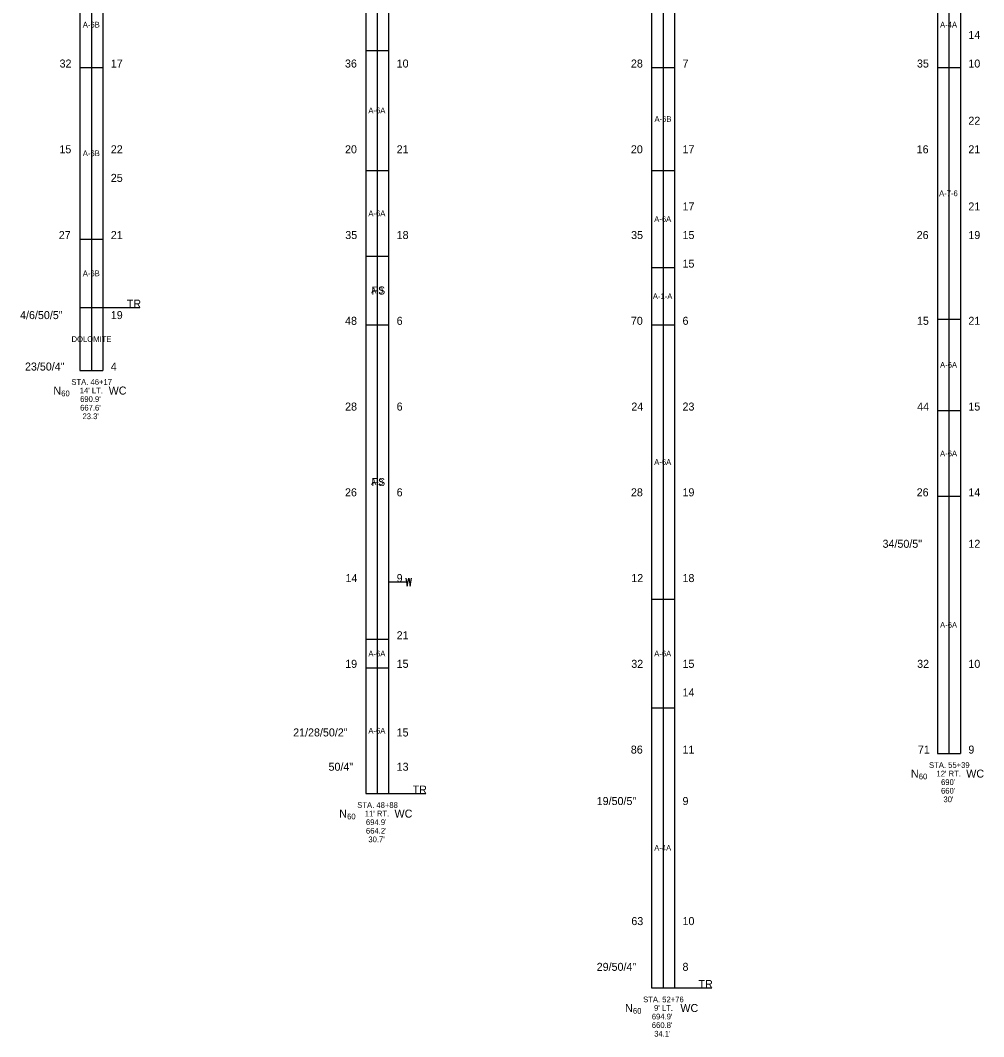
# Model space of a CAD drawing. Extents: x -1.2 to 16, y -0.9 to 35.
# Drawn here: x -1.24 to 15.61, y -0.85 to 16.93 of the extents above; entities that cross this region are included whole.
import ezdxf

# ---------------------------------------------------------------- set-up
doc = ezdxf.new("R2010")
doc.units = 0
for name, color, linetype in [('GT_Project_Cells', 7, 'Continuous'), ('GT_Project_Soil_Boring', 7, 'Continuous'), ('GT_Project_Soil_Layers', 7, 'Continuous'), ('GT_Project_Text', 7, 'Continuous'), ('SC_Scratch1', 7, 'Continuous'), ('SC_Scratch2', 7, 'Continuous')]:
    doc.layers.add(name, color=color, linetype=linetype)

msp = doc.modelspace()

# ---------------------------------------------------------------- linework, layer by layer
at = {"layer": 'GT_Project_Cells'}
msp.add_line((5.5, 7.1), (5.2, 7.1), dxfattribs=at)
msp.add_lwpolyline([(5.503, 7.171), (5.524, 7.031), (5.551, 7.171), (5.579, 7.031), (5.601, 7.171)], dxfattribs=at)
at = {"layer": 'GT_Project_Soil_Boring'}
for p, q in [((-0.2, 34.1), (-0.2, 10.8)), ((0, 34.1), (0, 10.8)), ((0.2, 34.1), (0.2, 10.8)), ((4.8, 34.1), (4.8, 3.4)), ((5, 34.1), (5, 3.4)), ((5.2, 34.1), (5.2, 3.4)), ((9.8, 34.1), (9.8, 0)), ((10, 34.1), (10, 0)), ((10.2, 34.1), (10.2, 0)), ((14.8, 34.1), (14.8, 4.1)), ((15, 34.1), (15, 4.1)), ((15.2, 34.1), (15.2, 4.1)), ((4.8, 16.4), (5.2, 16.4)), ((-0.2, 16.1), (0.2, 16.1)), ((9.8, 16.1), (10.2, 16.1)), ((14.8, 16.1), (15.2, 16.1)), ((4.8, 14.3), (5.2, 14.3)), ((9.8, 14.3), (10.2, 14.3)), ((-0.2, 13.1), (0.2, 13.1)), ((4.8, 12.8), (5.2, 12.8)), ((9.8, 12.6), (10.2, 12.6)), ((-0.2, 11.9), (0.2, 11.9)), ((4.8, 11.6), (5.2, 11.6)), ((9.8, 11.6), (10.2, 11.6)), ((14.8, 11.7), (15.2, 11.7)), ((-0.2, 10.8), (0.2, 10.8)), ((14.8, 10.1), (15.2, 10.1)), ((14.8, 8.6), (15.2, 8.6)), ((9.8, 6.8), (10.2, 6.8)), ((4.8, 6.1), (5.2, 6.1)), ((4.8, 5.6), (5.2, 5.6)), ((9.8, 4.9), (10.2, 4.9)), ((14.8, 4.1), (15.2, 4.1)), ((4.8, 3.4), (5.2, 3.4)), ((9.8, 0), (10.2, 0))]:
    msp.add_line(p, q, dxfattribs=at)
at = {"layer": 'GT_Project_Text'}
for p, q in [((0.2, 11.9), (0.85, 11.9)), ((-0.527, 10.45), (-0.527, 10.45)), ((14.473, 3.75), (14.473, 3.75)), ((5.2, 3.4), (5.85, 3.4)), ((4.473, 3.05), (4.473, 3.05)), ((10.2, 0), (10.85, 0)), ((9.473, -0.35), (9.473, -0.35))]:
    msp.add_line(p, q, dxfattribs=at)

# ---------------------------------------------------------------- texts
at = {"layer": 'GT_Project_Soil_Layers'}
for p in [(4.899, 12.13), (4.899, 8.78)]:
    msp.add_text('FS', height=0.14, dxfattribs=at).set_placement(p)
at = {"layer": 'GT_Project_Text'}
for s, height, p in [('14', 0.14, (15.34, 16.6)), ('32', 0.14, (-0.556, 16.1)), ('17', 0.14, (0.34, 16.1)), ('36', 0.14, (4.436, 16.1)), ('10', 0.14, (5.34, 16.1)), ('28', 0.14, (9.438, 16.1)), ('7', 0.14, (10.34, 16.1)), ('35', 0.14, (14.441, 16.1)), ('10', 0.14, (15.34, 16.1)), ('22', 0.14, (15.34, 15.1)), ('15', 0.14, (-0.559, 14.6)), ('22', 0.14, (0.34, 14.6)), ('20', 0.14, (4.437, 14.6)), ('21', 0.14, (5.34, 14.6)), ('20', 0.14, (9.437, 14.6)), ('17', 0.14, (10.34, 14.6)), ('16', 0.14, (14.436, 14.6)), ('21', 0.14, (15.34, 14.6)), ('25', 0.14, (0.34, 14.1)), ('17', 0.14, (10.34, 13.6)), ('21', 0.14, (15.34, 13.6)), ('27', 0.14, (-0.57, 13.1)), ('21', 0.14, (0.34, 13.1)), ('35', 0.14, (4.441, 13.1)), ('18', 0.14, (5.34, 13.1)), ('35', 0.14, (9.441, 13.1)), ('15', 0.14, (10.34, 13.1)), ('26', 0.14, (14.436, 13.1)), ('19', 0.14, (15.34, 13.1)), ('15', 0.14, (10.34, 12.6)), ('TR', 0.14, (0.62, 11.9)), ('4/6/50/5"', 0.14, (-1.247, 11.7)), ('19', 0.14, (0.34, 11.7)), ('48', 0.14, (4.438, 11.6)), ('6', 0.14, (5.34, 11.6)), ('70', 0.14, (9.437, 11.6)), ('6', 0.14, (10.34, 11.6)), ('15', 0.14, (14.441, 11.6)), ('21', 0.14, (15.34, 11.6)), ('23/50/4"', 0.14, (-1.161, 10.8)), ('4', 0.14, (0.34, 10.8)), ('N', 0.14, (-0.665, 10.38)), ('WC', 0.14, (0.303, 10.38)), ('60', 0.1, (-0.527, 10.35)), ('28', 0.14, (4.438, 10.1)), ('6', 0.14, (5.34, 10.1)), ('24', 0.14, (9.445, 10.1)), ('23', 0.14, (10.34, 10.1)), ('44', 0.14, (14.445, 10.1)), ('15', 0.14, (15.34, 10.1)), ('26', 0.14, (4.436, 8.6)), ('6', 0.14, (5.34, 8.6)), ('28', 0.14, (9.438, 8.6)), ('19', 0.14, (10.34, 8.6)), ('26', 0.14, (14.436, 8.6)), ('14', 0.14, (15.34, 8.6)), ('34/50/5"', 0.14, (13.839, 7.7)), ('12', 0.14, (15.34, 7.7)), ('14', 0.14, (4.445, 7.1)), ('9', 0.14, (5.34, 7.1)), ('12', 0.14, (9.444, 7.1)), ('18', 0.14, (10.34, 7.1)), ('21', 0.14, (5.34, 6.1)), ('19', 0.14, (4.44, 5.6)), ('15', 0.14, (5.34, 5.6)), ('32', 0.14, (9.444, 5.6)), ('15', 0.14, (10.34, 5.6)), ('32', 0.14, (14.444, 5.6)), ('10', 0.14, (15.34, 5.6)), ('14', 0.14, (10.34, 5.1)), ('21/28/50/2"', 0.14, (3.53, 4.4)), ('15', 0.14, (5.34, 4.4)), ('86', 0.14, (9.436, 4.1)), ('11', 0.14, (10.34, 4.1)), ('71', 0.14, (14.457, 4.1)), ('9', 0.14, (15.34, 4.1)), ('50/4"', 0.14, (4.148, 3.8)), ('13', 0.14, (5.34, 3.8)), ('N', 0.14, (14.335, 3.68)), ('60', 0.1, (14.473, 3.65)), ('WC', 0.14, (15.303, 3.68)), ('TR', 0.14, (5.62, 3.4)), ('19/50/5"', 0.14, (8.839, 3.2)), ('9', 0.14, (10.34, 3.2)), ('N', 0.14, (4.335, 2.98)), ('60', 0.1, (4.473, 2.95)), ('WC', 0.14, (5.303, 2.98)), ('63', 0.14, (9.445, 1.1)), ('10', 0.14, (10.34, 1.1)), ('29/50/4"', 0.14, (8.839, 0.3)), ('8', 0.14, (10.34, 0.3)), ('TR', 0.14, (10.62, 0)), ('N', 0.14, (9.335, -0.42)), ('60', 0.1, (9.473, -0.45)), ('WC', 0.14, (10.303, -0.42))]:
    msp.add_text(s, height=height, dxfattribs=at).set_placement(p)
at = {"layer": 'SC_Scratch1'}
for s, p in [('A-6B', (-0.15, 16.8)), ('A-4A', (14.845, 16.8)), ('A-6A', (4.845, 15.3)), ('A-6B', (9.85, 15.15)), ('A-6B', (-0.15, 14.55)), ('A-7-6', (14.828, 13.85)), ('A-6A', (4.845, 13.5)), ('A-6A', (9.845, 13.4)), ('A-6B', (-0.15, 12.45)), ('A-3', (4.894, 12.15)), ('A-1-A', (9.821, 12.05)), ('DOLOMITE', (-0.347, 11.3)), ('A-6A', (14.845, 10.85)), ('A-6A', (9.845, 9.15)), ('A-6A', (14.845, 9.3)), ('A-3', (4.894, 8.8)), ('A-6A', (14.845, 6.3)), ('A-6A', (4.845, 5.8)), ('A-6A', (9.845, 5.8)), ('A-6A', (4.845, 4.45)), ('A-4A', (9.845, 2.4))]:
    msp.add_text(s, height=0.1, dxfattribs=at).set_placement(p)
at = {"layer": 'SC_Scratch2'}
for s, p in [('STA. 46+17', (-0.349, 10.55)), ("14' LT.", (-0.203, 10.4)), ("690.9'", (-0.197, 10.25)), ("667.6'", (-0.197, 10.1)), ("23.3'", (-0.155, 9.95)), ('STA. 55+39', (14.652, 3.85)), ("12' RT.", (14.783, 3.7)), ("690'", (14.862, 3.55)), ("660'", (14.862, 3.4)), ('STA. 48+88', (4.651, 3.15)), ("30'", (14.904, 3.25)), ("11' RT.", (4.783, 3)), ("694.9'", (4.803, 2.85)), ("664.2'", (4.803, 2.7)), ("30.7'", (4.845, 2.55)), ('STA. 52+76', (9.651, -0.25)), ("9' LT.", (9.842, -0.4)), ("694.9'", (9.803, -0.55)), ("660.8'", (9.803, -0.7)), ("34.1'", (9.845, -0.85))]:
    msp.add_text(s, height=0.1, dxfattribs=at).set_placement(p)

doc.saveas('drawing.dxf')
